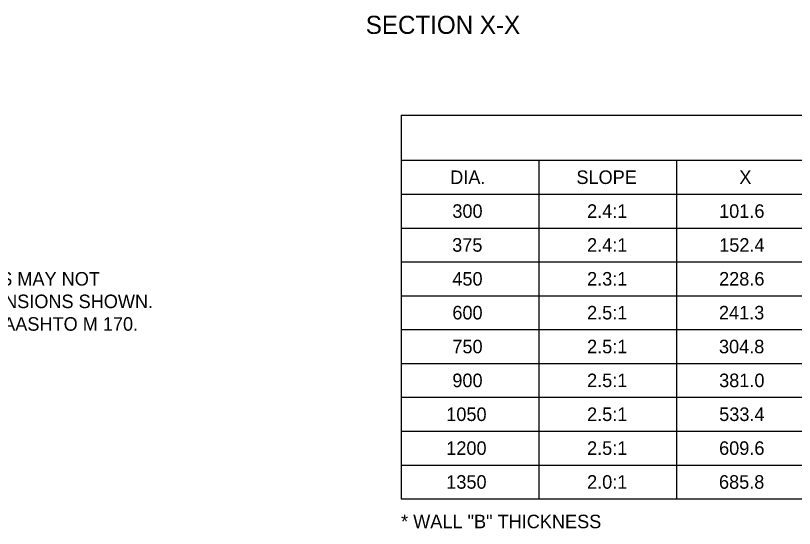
# Model space of a CAD drawing. Extents: x 49991.4 to 50022.1, y 49985 to 50011.4.
# Drawn here: x 50008.666 to 50012.115, y 49992.846 to 49995.118 of the extents above; entities that cross this region are included whole.
import ezdxf

# ---------------------------------------------------------------- set-up
doc = ezdxf.new("R2010")
doc.units = 0
doc.layers.add('Level 2', color=7, linetype='Continuous')

msp = doc.modelspace()

# ---------------------------------------------------------------- linework, layer by layer
at = {"layer": 'Level 2'}
for p, q in [((50010.3734, 49994.677), (50010.3734, 49992.977)), ((50010.3734, 49994.677), (50015.2534, 49994.677)), ((50010.3734, 49994.477), (50015.2534, 49994.477)), ((50010.9834, 49994.477), (50010.9834, 49992.977)), ((50011.5934, 49994.477), (50011.5934, 49992.977)), ((50010.3734, 49994.327), (50015.2534, 49994.327)), ((50010.3734, 49994.177), (50015.2534, 49994.177)), ((50010.3734, 49994.027), (50015.2534, 49994.027)), ((50010.3734, 49993.877), (50015.2534, 49993.877)), ((50010.3734, 49993.727), (50015.2534, 49993.727)), ((50010.3734, 49993.577), (50015.2534, 49993.577)), ((50010.3734, 49993.427), (50015.2534, 49993.427)), ((50010.3734, 49993.277), (50015.2534, 49993.277)), ((50010.3734, 49993.127), (50015.2534, 49993.127)), ((50010.3734, 49992.977), (50015.2534, 49992.977))]:
    msp.add_line(p, q, dxfattribs=at)

# ---------------------------------------------------------------- texts
for s, height, p in [('SECTION X-X', 0.08, (50010.2169, 49995.037)), ('DIA.', 0.06, (50010.5909, 49994.372)), ('SLOPE', 0.06, (50011.1496, 49994.372)), ('X', 0.06, (50011.871, 49994.372)), ('300', 0.06, (50010.6003, 49994.222)), ('2.4:1', 0.06, (50011.1967, 49994.222)), ('101.6', 0.06, (50011.7813, 49994.222)), ('375', 0.06, (50010.5996, 49994.072)), ('2.4:1', 0.06, (50011.1967, 49994.072)), ('152.4', 0.06, (50011.7818, 49994.072)), ('TOLERANCES IN THE ADJACENT TABLES MAY NOT', 0.06, (50007.047, 49993.922)), ('450', 0.06, (50010.6003, 49993.922)), ('2.3:1', 0.06, (50011.1967, 49993.922)), ('228.6', 0.06, (50011.7813, 49993.922)), ('VARY MORE THAN ±1.5% FOR THE DIMENSIONS SHOWN.', 0.06, (50007.047, 49993.822)), ('600', 0.06, (50010.6003, 49993.772)), ('2.5:1', 0.06, (50011.1967, 49993.772)), ('241.3', 0.06, (50011.7806, 49993.772)), ('OTHERWISE THEY MUST CONFORM TO AASHTO M 170.', 0.06, (50007.047, 49993.722)), ('750', 0.06, (50010.6003, 49993.622)), ('2.5:1', 0.06, (50011.1967, 49993.622)), ('304.8', 0.06, (50011.7808, 49993.622)), ('900', 0.06, (50010.6003, 49993.472)), ('2.5:1', 0.06, (50011.1967, 49993.472)), ('381.0', 0.06, (50011.7815, 49993.472)), ('1050', 0.06, (50010.5733, 49993.322)), ('2.5:1', 0.06, (50011.1967, 49993.322)), ('533.4', 0.06, (50011.7818, 49993.322)), ('1200', 0.06, (50010.5733, 49993.172)), ('2.5:1', 0.06, (50011.1967, 49993.172)), ('609.6', 0.06, (50011.7813, 49993.172)), ('1350', 0.06, (50010.5733, 49993.022)), ('2.0:1', 0.06, (50011.1967, 49993.022)), ('685.8', 0.06, (50011.7808, 49993.022)), ('* WALL "B" THICKNESS', 0.06, (50010.3734, 49992.847))]:
    msp.add_text(s, height=height, dxfattribs=at).set_placement(p)

doc.saveas('drawing.dxf')
